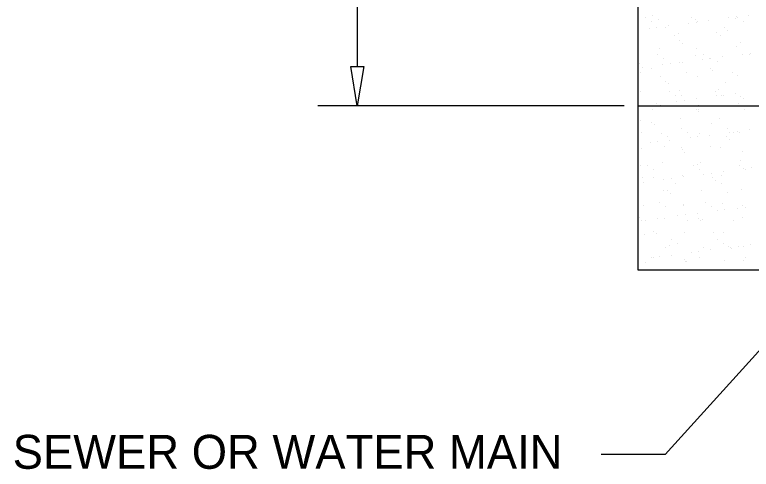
# Model space of a CAD drawing. Extents: x -118779 to -116979, y -104389 to -102939.
# Drawn here: x -117707.6 to -117577.5, y -103376.7 to -103296.4 of the extents above; entities that cross this region are included whole.
import ezdxf

# ---------------------------------------------------------------- set-up
doc = ezdxf.new("R2010")
doc.units = 0
for name, color, linetype in [('G-MARK', 7, 'Continuous'), ('G-TEXT', 7, 'Continuous'), ('Misc CnstDet(22)', 7, 'Continuous')]:
    doc.layers.add(name, color=color, linetype=linetype)

msp = doc.modelspace()

# ---------------------------------------------------------------- linework, layer by layer
at = {"layer": 'G-MARK'}
for p, q in [((-117647.13, -103155.31), (-117647.13, -103305.52)), ((-117599.93, -103312.48), (-117654.09, -103312.48))]:
    msp.add_line(p, q, dxfattribs=at)
msp.add_lwpolyline([(-117533.5, -103308.81), (-117592.7, -103374.11), (-117604.01, -103374.11)], dxfattribs=at)
at = {"layer": 'G-TEXT'}
msp.add_lwpolyline([(-117648.26, -103305.52), (-117645.96, -103305.52), (-117647.13, -103312.48)], close=True, dxfattribs=at)
at = {"layer": 'Misc CnstDet(22)'}
for p, q in [((-117597.5, -103148.35), (-117597.5, -103341.51)), ((-117577.96, -103296.47), (-117577.96, -103296.47)), ((-117596.13, -103296.88), (-117596.13, -103296.88)), ((-117595.03, -103297.56), (-117595.03, -103297.56)), ((-117594.93, -103296.54), (-117594.93, -103296.54)), ((-117593.93, -103297.29), (-117593.93, -103297.29)), ((-117588, -103296.84), (-117588, -103296.84)), ((-117587.25, -103297.29), (-117587.25, -103297.29)), ((-117587.11, -103297.7), (-117587.11, -103297.7)), ((-117586.9, -103297.56), (-117586.9, -103297.56)), ((-117585.02, -103297.39), (-117585.02, -103297.39)), ((-117581.45, -103296.95), (-117581.45, -103296.95)), ((-117580.19, -103297.05), (-117580.19, -103297.05)), ((-117580.08, -103296.78), (-117580.08, -103296.78)), ((-117579.88, -103296.84), (-117579.88, -103296.84)), ((-117578.78, -103297.56), (-117578.78, -103297.56)), ((-117595.51, -103298.8), (-117595.51, -103298.8)), ((-117594.17, -103298.63), (-117594.17, -103298.63)), ((-117592.66, -103298.63), (-117592.66, -103298.63)), ((-117592.05, -103298.32), (-117592.05, -103298.32)), ((-117588.48, -103297.87), (-117588.48, -103297.87)), ((-117582.21, -103298.7), (-117582.21, -103298.7)), ((-117597.43, -103299.96), (-117597.43, -103299.96)), ((-117591.09, -103300.1), (-117591.09, -103300.1)), ((-117590.37, -103299.72), (-117590.37, -103299.72)), ((-117583.55, -103299.62), (-117583.55, -103299.62)), ((-117582.93, -103300.1), (-117582.93, -103300.1)), ((-117581.73, -103299.14), (-117581.73, -103299.14)), ((-117590.06, -103300.99), (-117590.06, -103300.99)), ((-117589.58, -103301.44), (-117589.58, -103301.44)), ((-117579.43, -103301.23), (-117579.43, -103301.23)), ((-117593.76, -103302.29), (-117593.76, -103302.29)), ((-117587.08, -103302.33), (-117587.08, -103302.33)), ((-117580.01, -103302.09), (-117580.01, -103302.09)), ((-117597.43, -103303.73), (-117597.43, -103303.73)), ((-117594.03, -103303.43), (-117594.03, -103303.43)), ((-117592.94, -103304.11), (-117592.94, -103304.11)), ((-117587.28, -103303.53), (-117587.28, -103303.53)), ((-117586.08, -103304.32), (-117586.08, -103304.32)), ((-117585.91, -103303.39), (-117585.91, -103303.39)), ((-117584.81, -103304.11), (-117584.81, -103304.11)), ((-117584.71, -103304.15), (-117584.71, -103304.15)), ((-117582.59, -103303.84), (-117582.59, -103303.84)), ((-117579.05, -103303.39), (-117579.05, -103303.39)), ((-117577.75, -103303.39), (-117577.75, -103303.39)), ((-117577.68, -103303.22), (-117577.68, -103303.22)), ((-117597.26, -103305), (-117597.26, -103305)), ((-117593.11, -103305.24), (-117593.11, -103305.24)), ((-117591.74, -103305.07), (-117591.74, -103305.07)), ((-117590.23, -103304.76), (-117590.23, -103304.76)), ((-117589.61, -103304.76), (-117589.61, -103304.76)), ((-117583.37, -103304.66), (-117583.37, -103304.66)), ((-117597.08, -103306.65), (-117597.08, -103306.65)), ((-117596.64, -103305.69), (-117596.64, -103305.69)), ((-117595.17, -103305.83), (-117595.17, -103305.83)), ((-117588.96, -103306.65), (-117588.96, -103306.65)), ((-117584.71, -103305.89), (-117584.71, -103305.89)), ((-117584.23, -103306.34), (-117584.23, -103306.34)), ((-117580.84, -103306.61), (-117580.84, -103306.61)), ((-117593.59, -103307.33), (-117593.59, -103307.33)), ((-117592.56, -103308.19), (-117592.56, -103308.19)), ((-117586.9, -103307.37), (-117586.9, -103307.37)), ((-117579.84, -103307.13), (-117579.84, -103307.13)), ((-117592.08, -103308.64), (-117592.08, -103308.64)), ((-117581.93, -103308.43), (-117581.93, -103308.43)), ((-117597.12, -103310.04), (-117597.12, -103310.04)), ((-117591.91, -103309.97), (-117591.91, -103309.97)), ((-117590.81, -103310.66), (-117590.81, -103310.66)), ((-117590.06, -103309.8), (-117590.06, -103309.8)), ((-117589.78, -103310.73), (-117589.78, -103310.73)), ((-117583.79, -103309.94), (-117583.79, -103309.94)), ((-117583.68, -103310.76), (-117583.68, -103310.76)), ((-117583.2, -103309.7), (-117583.2, -103309.7)), ((-117582.69, -103310.66), (-117582.69, -103310.66)), ((-117582.31, -103310.59), (-117582.31, -103310.59)), ((-117580.19, -103310.28), (-117580.19, -103310.28)), ((-117579.33, -103310.8), (-117579.33, -103310.8)), ((-117590.71, -103311.69), (-117590.71, -103311.69)), ((-117589.34, -103311.52), (-117589.34, -103311.52)), ((-117587.21, -103311.21), (-117587.21, -103311.21)), ((-117578.85, -103311.24), (-117578.85, -103311.24)), ((-117647.13, -103312.48), (-117647.13, -103312.48)), ((-117597.5, -103312.48), (-117536.07, -103312.48)), ((-117597.5, -103312.48), (-117597.5, -103312.48)), ((-117596.37, -103312.44), (-117596.37, -103312.44)), ((-117594.99, -103313.19), (-117594.99, -103313.19)), ((-117594.24, -103312.17), (-117594.24, -103312.17)), ((-117593.42, -103312.37), (-117593.42, -103312.37)), ((-117587.18, -103313.09), (-117587.18, -103313.09)), ((-117586.87, -103313.19), (-117586.87, -103313.19)), ((-117586.73, -103312.41), (-117586.73, -103312.41)), ((-117579.67, -103312.17), (-117579.67, -103312.17)), ((-117578.71, -103313.16), (-117578.71, -103313.16)), ((-117586.7, -103313.54), (-117586.7, -103313.54)), ((-117583.07, -103314.74), (-117583.07, -103314.74)), ((-117596.95, -103315.08), (-117596.95, -103315.08)), ((-117595.06, -103315.39), (-117595.06, -103315.39)), ((-117594.58, -103315.83), (-117594.58, -103315.83)), ((-117589.89, -103314.81), (-117589.89, -103314.81)), ((-117584.44, -103315.63), (-117584.44, -103315.63)), ((-117596.84, -103317.21), (-117596.84, -103317.21)), ((-117589.82, -103316.49), (-117589.82, -103316.49)), ((-117588.72, -103317.21), (-117588.72, -103317.21)), ((-117581.69, -103316.49), (-117581.69, -103316.49)), ((-117581.25, -103317.21), (-117581.25, -103317.21)), ((-117580.56, -103317.17), (-117580.56, -103317.17)), ((-117579.91, -103317.03), (-117579.91, -103317.03)), ((-117579.53, -103317.17), (-117579.53, -103317.17)), ((-117577.79, -103316.76), (-117577.79, -103316.76)), ((-117593.25, -103317.41), (-117593.25, -103317.41)), ((-117592.29, -103317.93), (-117592.29, -103317.93)), ((-117591.84, -103318.61), (-117591.84, -103318.61)), ((-117588.28, -103318.13), (-117588.28, -103318.13)), ((-117586.94, -103317.96), (-117586.94, -103317.96)), ((-117586.56, -103317.45), (-117586.56, -103317.45)), ((-117584.81, -103317.69), (-117584.81, -103317.69)), ((-117581.83, -103317.99), (-117581.83, -103317.99)), ((-117581.35, -103318.44), (-117581.35, -103318.44)), ((-117595.34, -103319.06), (-117595.34, -103319.06)), ((-117593.97, -103318.88), (-117593.97, -103318.88)), ((-117592.87, -103319.74), (-117592.87, -103319.74)), ((-117589.72, -103319.84), (-117589.72, -103319.84)), ((-117584.75, -103319.71), (-117584.75, -103319.71)), ((-117582.89, -103319.78), (-117582.89, -103319.78)), ((-117596.78, -103320.12), (-117596.78, -103320.12)), ((-117589.68, -103320.29), (-117589.68, -103320.29)), ((-117589.2, -103320.74), (-117589.2, -103320.74)), ((-117579.09, -103320.53), (-117579.09, -103320.53)), ((-117593.11, -103322.45), (-117593.11, -103322.45)), ((-117586.42, -103322.48), (-117586.42, -103322.48)), ((-117579.36, -103322.21), (-117579.36, -103322.21)), ((-117597.05, -103323.03), (-117597.05, -103323.03)), ((-117595.85, -103323.07), (-117595.85, -103323.07)), ((-117594.72, -103323.75), (-117594.72, -103323.75)), ((-117587.69, -103323.03), (-117587.69, -103323.03)), ((-117586.94, -103322.83), (-117586.94, -103322.83)), ((-117586.6, -103323.75), (-117586.6, -103323.75)), ((-117579.57, -103323.03), (-117579.57, -103323.03)), ((-117578.85, -103323.65), (-117578.85, -103323.65)), ((-117578.47, -103323.72), (-117578.47, -103323.72)), ((-117577.48, -103323.48), (-117577.48, -103323.48)), ((-117596.61, -103325.16), (-117596.61, -103325.16)), ((-117594.79, -103325.12), (-117594.79, -103325.12)), ((-117589.54, -103324.88), (-117589.54, -103324.88)), ((-117589.44, -103325.05), (-117589.44, -103325.05)), ((-117585.88, -103324.57), (-117585.88, -103324.57)), ((-117584.54, -103324.4), (-117584.54, -103324.4)), ((-117582.72, -103324.81), (-117582.72, -103324.81)), ((-117582.41, -103324.13), (-117582.41, -103324.13)), ((-117596.47, -103325.98), (-117596.47, -103325.98)), ((-117592.9, -103325.5), (-117592.9, -103325.5)), ((-117591.57, -103325.33), (-117591.57, -103325.33)), ((-117590.78, -103326.29), (-117590.78, -103326.29)), ((-117584.33, -103325.19), (-117584.33, -103325.19)), ((-117583.85, -103325.64), (-117583.85, -103325.64)), ((-117582.65, -103326.25), (-117582.65, -103326.25)), ((-117592.94, -103327.45), (-117592.94, -103327.45)), ((-117592.18, -103327.49), (-117592.18, -103327.49)), ((-117586.25, -103327.49), (-117586.25, -103327.49)), ((-117581.59, -103327.73), (-117581.59, -103327.73)), ((-117579.19, -103327.25), (-117579.19, -103327.25)), ((-117591.7, -103327.93), (-117591.7, -103327.93)), ((-117596.43, -103330.16), (-117596.43, -103330.16)), ((-117593.73, -103329.58), (-117593.73, -103329.58)), ((-117592.63, -103330.3), (-117592.63, -103330.3)), ((-117589.44, -103330.03), (-117589.44, -103330.03)), ((-117589.41, -103329.92), (-117589.41, -103329.92)), ((-117585.6, -103329.58), (-117585.6, -103329.58)), ((-117584.51, -103330.27), (-117584.51, -103330.27)), ((-117582.55, -103329.82), (-117582.55, -103329.82)), ((-117578.99, -103330.09), (-117578.99, -103330.09)), ((-117587.01, -103331.5), (-117587.01, -103331.5)), ((-117583.48, -103331.02), (-117583.48, -103331.02)), ((-117582.11, -103330.85), (-117582.11, -103330.85)), ((-117579.98, -103330.57), (-117579.98, -103330.57)), ((-117578.51, -103330.54), (-117578.51, -103330.54)), ((-117597.29, -103332.32), (-117597.29, -103332.32)), ((-117596.81, -103332.84), (-117596.81, -103332.84)), ((-117596.19, -103332.7), (-117596.19, -103332.7)), ((-117594.07, -103332.42), (-117594.07, -103332.42)), ((-117592.77, -103332.49), (-117592.77, -103332.49)), ((-117590.5, -103331.94), (-117590.5, -103331.94)), ((-117589.13, -103331.77), (-117589.13, -103331.77)), ((-117588.65, -103332.84), (-117588.65, -103332.84)), ((-117586.84, -103332.39), (-117586.84, -103332.39)), ((-117586.36, -103332.84), (-117586.36, -103332.84)), ((-117586.08, -103332.53), (-117586.08, -103332.53)), ((-117580.53, -103332.8), (-117580.53, -103332.8)), ((-117579.02, -103332.29), (-117579.02, -103332.29)), ((-117596.3, -103335.2), (-117596.3, -103335.2)), ((-117594.69, -103334.69), (-117594.69, -103334.69)), ((-117594.21, -103335.13), (-117594.21, -103335.13)), ((-117589.24, -103334.96), (-117589.24, -103334.96)), ((-117584.09, -103334.93), (-117584.09, -103334.93)), ((-117582.38, -103334.86), (-117582.38, -103334.86)), ((-117591.63, -103336.13), (-117591.63, -103336.13)), ((-117590.5, -103336.85), (-117590.5, -103336.85)), ((-117583.48, -103336.13), (-117583.48, -103336.13)), ((-117582.38, -103336.81), (-117582.38, -103336.81)), ((-117592.59, -103337.53), (-117592.59, -103337.53)), ((-117591.94, -103337.22), (-117591.94, -103337.22)), ((-117585.91, -103337.57), (-117585.91, -103337.57)), ((-117584.61, -103337.94), (-117584.61, -103337.94)), ((-117581.49, -103337.29), (-117581.49, -103337.29)), ((-117581.08, -103337.46), (-117581.08, -103337.46)), ((-117581.01, -103337.74), (-117581.01, -103337.74)), ((-117579.71, -103337.29), (-117579.71, -103337.29)), ((-117578.85, -103337.33), (-117578.85, -103337.33)), ((-117577.58, -103337.02), (-117577.58, -103337.02)), ((-117595.13, -103339.31), (-117595.13, -103339.31)), ((-117594.69, -103339.38), (-117594.69, -103339.38)), ((-117593.76, -103339.14), (-117593.76, -103339.14)), ((-117591.63, -103338.87), (-117591.63, -103338.87)), ((-117588.1, -103338.39), (-117588.1, -103338.39)), ((-117586.73, -103338.22), (-117586.73, -103338.22)), ((-117586.56, -103339.35), (-117586.56, -103339.35)), ((-117578.4, -103339.35), (-117578.4, -103339.35)), ((-117596.13, -103340.24), (-117596.13, -103340.24)), ((-117589.34, -103339.59), (-117589.34, -103339.59)), ((-117589.06, -103340), (-117589.06, -103340)), ((-117588.86, -103340.03), (-117588.86, -103340.03)), ((-117582.24, -103339.9), (-117582.24, -103339.9)), ((-117578.75, -103339.83), (-117578.75, -103339.83)), ((-117597.5, -103341.51), (-117422.06, -103341.51))]:
    msp.add_line(p, q, dxfattribs=at)

# ---------------------------------------------------------------- texts
msp.add_text('SEWER OR WATER MAIN', height=6, dxfattribs=at).set_placement((-117708, -103376.65))

doc.saveas('drawing.dxf')
